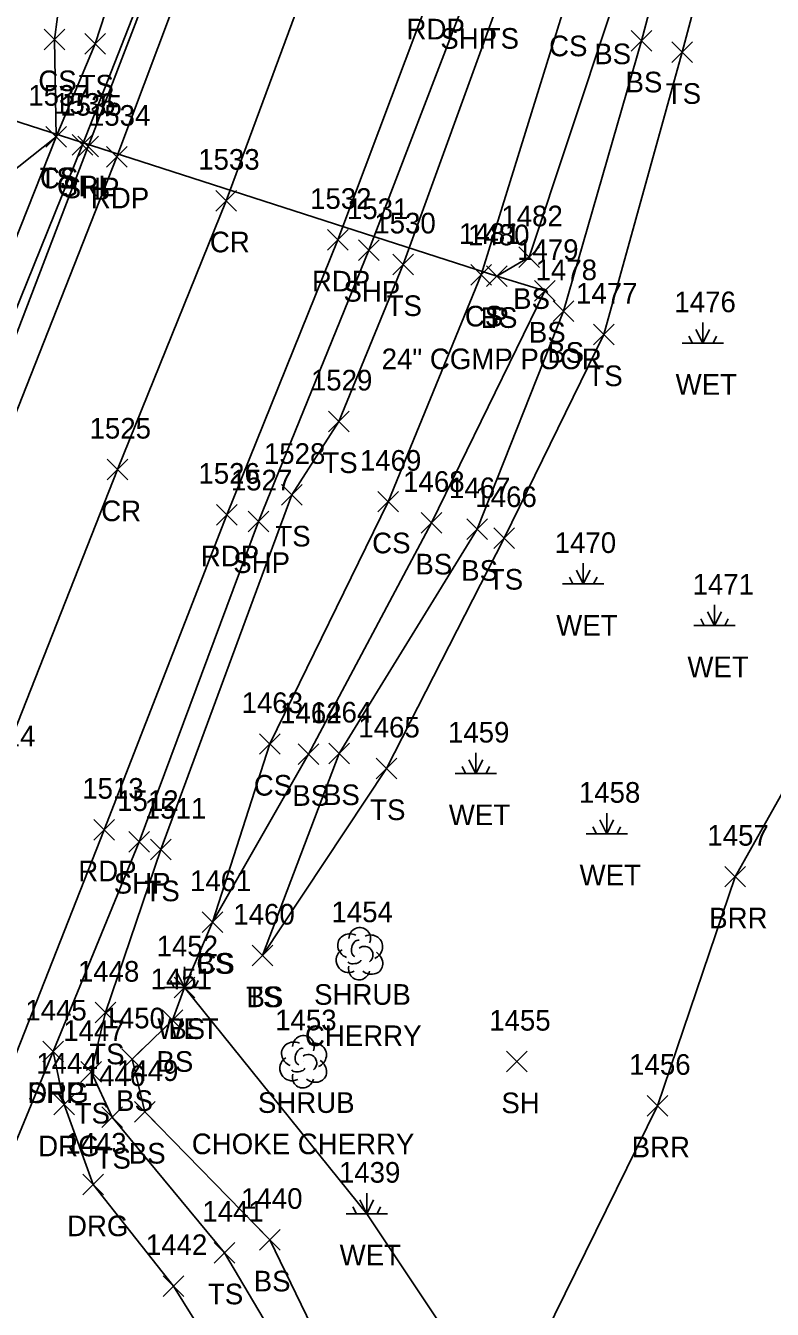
# Model space of a CAD drawing. Extents: x 1554917 to 1555870, y 813367 to 816333.
# Drawn here: x 1555209.2 to 1555281.5, y 813931.9 to 814056.2 of the extents above; entities that cross this region are included whole.
import ezdxf

# ---------------------------------------------------------------- set-up
doc = ezdxf.new("R2010")
doc.units = 0
for name, color, linetype in [('D_A', 7, 'Continuous'), ('D_C', 7, 'Continuous'), ('D_I', 7, 'Continuous'), ('D_TIC', 7, 'Continuous'), ('DCP', 7, 'Continuous'), ('L_A', 7, 'Continuous'), ('L_C', 7, 'Continuous'), ('L_I', 7, 'Continuous'), ('L_TIC', 7, 'Continuous'), ('LABL', 7, 'Continuous'), ('LELB', 7, 'Continuous'), ('LSH', 7, 'Continuous'), ('LWET', 7, 'Continuous'), ('P_A', 7, 'Continuous'), ('P_I', 7, 'Continuous'), ('P_TIC', 7, 'Continuous'), ('PET', 7, 'Continuous'), ('PRC', 7, 'Continuous'), ('PSP', 7, 'Continuous'), ('R_A', 7, 'Continuous'), ('R_I', 7, 'Continuous'), ('R_TIC', 7, 'Continuous'), ('RDG', 7, 'Continuous'), ('RGR', 7, 'Continuous')]:
    doc.layers.add(name, color=color, linetype=linetype)

msp = doc.modelspace()

# ---------------------------------------------------------------- linework, layer by layer
at = {"layer": 'D_TIC'}
for points in [[(1555253.85, 814030.94), (1555255.85, 814032.94)], [(1555255.85, 814030.94), (1555253.85, 814032.94)]]:
    msp.add_lwpolyline(points, dxfattribs=at)
at = {"layer": 'DCP'}
msp.add_lwpolyline([(1555254.85, 814031.94), (1555184.15, 814054.74)], dxfattribs=at)
at = {"layer": 'L_TIC'}
for points in [[(1555211.03, 814053.87), (1555213.03, 814055.87)], [(1555213.03, 814053.87), (1555211.03, 814055.87)], [(1555267.88, 814053.75), (1555269.88, 814055.75)], [(1555269.88, 814053.75), (1555267.88, 814055.75)], [(1555214.96, 814053.45), (1555216.96, 814055.45)], [(1555216.96, 814053.45), (1555214.96, 814055.45)], [(1555271.81, 814052.64), (1555273.81, 814054.64)], [(1555273.81, 814052.64), (1555271.81, 814054.64)], [(1555211.19, 814044.46), (1555213.19, 814046.46)], [(1555213.19, 814044.46), (1555211.19, 814046.46)], [(1555211.19, 814044.46), (1555213.19, 814046.46)], [(1555213.19, 814044.46), (1555211.19, 814046.46)], [(1555211.19, 814044.46), (1555213.19, 814046.46)], [(1555213.19, 814044.46), (1555211.19, 814046.46)], [(1555257, 814032.78), (1555259, 814034.78)], [(1555259, 814032.78), (1555257, 814034.78)], [(1555244.78, 814032.09), (1555246.78, 814034.09)], [(1555246.78, 814032.09), (1555244.78, 814034.09)], [(1555252.33, 814031.08), (1555254.33, 814033.08)], [(1555254.33, 814031.08), (1555252.33, 814033.08)], [(1555253.85, 814030.94), (1555255.85, 814032.94)], [(1555255.85, 814030.94), (1555253.85, 814032.94)], [(1555258.52, 814029.52), (1555260.52, 814031.52)], [(1555260.52, 814029.52), (1555258.52, 814031.52)], [(1555260.3, 814027.56), (1555262.3, 814029.56)], [(1555262.3, 814027.56), (1555260.3, 814029.56)], [(1555264.22, 814025.3), (1555266.22, 814027.3)], [(1555266.22, 814025.3), (1555264.22, 814027.3)], [(1555238.56, 814016.88), (1555240.56, 814018.88)], [(1555240.56, 814016.88), (1555238.56, 814018.88)], [(1555234.01, 814009.77), (1555236.01, 814011.77)], [(1555236.01, 814009.77), (1555234.01, 814011.77)], [(1555243.35, 814009.11), (1555245.35, 814011.11)], [(1555245.35, 814009.11), (1555243.35, 814011.11)], [(1555247.53, 814007.06), (1555249.53, 814009.06)], [(1555249.53, 814007.06), (1555247.53, 814009.06)], [(1555251.97, 814006.45), (1555253.97, 814008.45)], [(1555253.97, 814006.45), (1555251.97, 814008.45)], [(1555254.58, 814005.59), (1555256.58, 814007.59)], [(1555256.58, 814005.59), (1555254.58, 814007.59)], [(1555231.89, 813985.64), (1555233.89, 813987.64)], [(1555233.89, 813985.64), (1555231.89, 813987.64)], [(1555235.62, 813984.65), (1555237.62, 813986.65)], [(1555237.62, 813984.65), (1555235.62, 813986.65)], [(1555238.59, 813984.72), (1555240.59, 813986.72)], [(1555240.59, 813984.72), (1555238.59, 813986.72)], [(1555243.19, 813983.27), (1555245.19, 813985.27)], [(1555245.19, 813983.27), (1555243.19, 813985.27)], [(1555221.34, 813975.41), (1555223.34, 813977.41)], [(1555223.34, 813975.41), (1555221.34, 813977.41)], [(1555276.93, 813972.79), (1555278.93, 813974.79)], [(1555278.93, 813972.79), (1555276.93, 813974.79)], [(1555226.33, 813968.39), (1555228.33, 813970.39)], [(1555228.33, 813968.39), (1555226.33, 813970.39)], [(1555226.33, 813968.39), (1555228.33, 813970.39)], [(1555228.33, 813968.39), (1555226.33, 813970.39)], [(1555231.18, 813965.15), (1555233.18, 813967.15)], [(1555233.18, 813965.15), (1555231.18, 813967.15)], [(1555231.18, 813965.15), (1555233.18, 813967.15)], [(1555233.18, 813965.15), (1555231.18, 813967.15)], [(1555223.61, 813962.07), (1555225.61, 813964.07)], [(1555225.61, 813962.07), (1555223.61, 813964.07)], [(1555215.99, 813959.62), (1555217.99, 813961.62)], [(1555217.99, 813959.62), (1555215.99, 813961.62)], [(1555222.47, 813958.89), (1555224.47, 813960.89)], [(1555224.47, 813958.89), (1555222.47, 813960.89)], [(1555218.56, 813955.1), (1555220.56, 813957.1)], [(1555220.56, 813955.1), (1555218.56, 813957.1)], [(1555255.81, 813954.88), (1555257.81, 813956.88)], [(1555257.81, 813954.88), (1555255.81, 813956.88)], [(1555214.58, 813953.88), (1555216.58, 813955.88)], [(1555216.58, 813953.88), (1555214.58, 813955.88)], [(1555269.42, 813950.6), (1555271.42, 813952.6)], [(1555271.42, 813950.6), (1555269.42, 813952.6)], [(1555216.61, 813949.51), (1555218.61, 813951.51)], [(1555218.61, 813949.51), (1555216.61, 813951.51)], [(1555219.79, 813950), (1555221.79, 813952)], [(1555221.79, 813950), (1555219.79, 813952)], [(1555231.88, 813937.62), (1555233.88, 813939.62)], [(1555233.88, 813937.62), (1555231.88, 813939.62)], [(1555227.48, 813936.37), (1555229.48, 813938.37)], [(1555229.48, 813936.37), (1555227.48, 813938.37)]]:
    msp.add_lwpolyline(points, dxfattribs=at)
at = {"layer": 'LABL'}
msp.add_lwpolyline([(1555246.98, 813903.97), (1555255.51, 813921.27), (1555270.42, 813951.6), (1555277.93, 813973.79), (1555289.33, 813994.04), (1555300.33, 814008.73), (1555305.54, 814022.92), (1555313.64, 814041.1), (1555318.32, 814081.03), (1555326.1, 814100.25), (1555336, 814125.43)], dxfattribs=at)
at = {"layer": 'LELB'}
for points in [[(1555161.57, 813925.65), (1555168.92, 813938.89), (1555173.57, 813945.95), (1555174.16, 813952.01), (1555182.4, 813974.26), (1555190.04, 813992.11), (1555201.74, 814019.14), (1555212.19, 814045.46), (1555215.96, 814054.45), (1555221.93, 814072.78), (1555233.01, 814105.58), (1555244.12, 814126.91), (1555239.17, 814141.42), (1555241.48, 814149.75), (1555239.8, 814159.84), (1555236.73, 814168.01), (1555231.65, 814185.57), (1555238.6, 814201.71), (1555239.91, 814224.12), (1555242.5, 814231.73), (1555248.59, 814255.34), (1555259.33, 814293.88), (1555265.42, 814329.58), (1555267.14, 814335.72)], [(1555244.11, 813903.09), (1555240.76, 813916.62), (1555228.48, 813937.37), (1555217.61, 813950.51), (1555215.58, 813954.88), (1555216.99, 813960.62), (1555222.34, 813976.41), (1555235.01, 814010.77), (1555239.56, 814017.88), (1555245.78, 814033.09), (1555255.18, 814058.98), (1555268.47, 814094.07), (1555274.97, 814112.22), (1555278.17, 814116.24), (1555282.02, 814117.52), (1555286.39, 814116.11), (1555289.99, 814109.88), (1555296.54, 814106.47), (1555313.61, 814126.36), (1555333.57, 814137.64)], [(1555246.98, 813903.97), (1555242.99, 813917.76), (1555232.88, 813938.62), (1555220.79, 813951), (1555219.56, 813956.1), (1555223.47, 813959.89), (1555224.61, 813963.07), (1555227.33, 813969.39), (1555236.62, 813985.65), (1555248.53, 814008.06), (1555259.52, 814030.52), (1555254.85, 814031.94), (1555258, 814033.78), (1555265.85, 814057.48), (1555276.22, 814093.19), (1555280.35, 814112.31), (1555282.12, 814115.72), (1555282.41, 814111.98), (1555282.34, 814108.27)], [(1555232.18, 813966.15), (1555239.59, 813985.72), (1555252.97, 814007.45), (1555261.3, 814028.56), (1555268.88, 814054.75), (1555278.5, 814091.24), (1555282.34, 814108.27)], [(1555212.19, 814045.46), (1555212.03, 814054.87), (1555214.66, 814074.66), (1555228.74, 814107.66)], [(1555232.18, 813966.15), (1555244.19, 813984.27), (1555255.58, 814006.59), (1555265.22, 814026.3), (1555272.81, 814053.64), (1555282.57, 814090.32), (1555287.82, 814106.78)], [(1555227.33, 813969.39), (1555232.89, 813986.64), (1555244.35, 814010.11), (1555253.33, 814032.08), (1555261.48, 814058.25), (1555272.51, 814095.22)], [(1555212.19, 814045.46), (1555204.95, 814039.71), (1555197.69, 814022.43), (1555191.66, 814010.7), (1555185.66, 813993.85), (1555179.53, 813983.39), (1555173.8, 813970.81), (1555169.92, 813961.29), (1555164.03, 813953.38)]]:
    msp.add_lwpolyline(points, dxfattribs=at)
at = {"layer": 'LSH'}
for p, q in [((1555241.54, 813966.38), (1555241.54, 813966.38)), ((1555241.54, 813966.38), (1555241.54, 813966.38)), ((1555236.1, 813955.91), (1555236.1, 813955.91)), ((1555236.1, 813955.91), (1555236.1, 813955.91))]:
    msp.add_line(p, q, dxfattribs=at)
for centre in [(1555241.59, 813967.81), (1555236.14, 813957.35)]:
    msp.add_arc(centre, 1.05, 335.5272, 180.9563, dxfattribs=at)
for centre, major_axis, ratio, start_param, end_param in [((1555240.75, 813967.05), (1.21, -0.51), 0.895232, 1.570796, 4.712389), ((1555241.33, 813966.84), (-0.208, -0.792), 0.645439, 3.141593, 6.283185), ((1555242.58, 813966.96), (-1.14, -0.48), 0.949671, 1.570796, 4.712389), ((1555240.46, 813965.67), (0.58, -1.04), 0.959034, 3.141593, 6.283185), ((1555242.04, 813966.21), (-0.5, 0.667), 0.989748, 3.141593, 6.283185), ((1555242.54, 813965.55), (-1.09, 0.79), 0.841452, 1.570796, 4.712389), ((1555241.54, 813964.88), (0.26, 1.06), 0.942809, 1.570796, 4.712389), ((1555241.08, 813965.63), (-0.625, -0.083), 0.423636, 0, 3.141593), ((1555235.31, 813956.58), (1.21, -0.51), 0.895232, 1.570796, 4.712389), ((1555237.14, 813956.49), (-1.14, -0.48), 0.949671, 1.570796, 4.712389), ((1555235.01, 813955.2), (0.58, -1.04), 0.959034, 3.141593, 6.283185), ((1555235.89, 813956.37), (-0.208, -0.792), 0.645439, 3.141593, 6.283185), ((1555236.6, 813955.74), (-0.5, 0.667), 0.989748, 3.141593, 6.283185), ((1555235.64, 813955.16), (-0.625, -0.083), 0.423636, 0, 3.141593), ((1555237.1, 813955.08), (-1.09, 0.79), 0.841452, 1.570796, 4.712389), ((1555236.1, 813954.41), (0.26, 1.06), 0.942809, 1.570796, 4.712389)]:
    msp.add_ellipse(centre, major_axis=major_axis, ratio=ratio, start_param=start_param, end_param=end_param, dxfattribs=at)
at = {"layer": 'LWET'}
for p, q in [((1555274.8, 814025.46), (1555274.8, 814027.46)), ((1555273.8, 814025.46), (1555273.46, 814026.13)), ((1555274.8, 814025.46), (1555274.13, 814026.79)), ((1555274.8, 814025.46), (1555275.46, 814026.79)), ((1555275.8, 814025.46), (1555276.13, 814026.13)), ((1555276.8, 814025.46), (1555272.8, 814025.46)), ((1555263.23, 814002.14), (1555262.57, 814003.47)), ((1555263.23, 814002.14), (1555263.23, 814004.14)), ((1555263.23, 814002.14), (1555263.9, 814003.47)), ((1555265.23, 814002.14), (1555261.23, 814002.14)), ((1555262.23, 814002.14), (1555261.9, 814002.8)), ((1555264.23, 814002.14), (1555264.57, 814002.8)), ((1555275.94, 813998.11), (1555275.94, 814000.11)), ((1555274.94, 813998.11), (1555274.6, 813998.77)), ((1555275.94, 813998.11), (1555275.27, 813999.44)), ((1555275.94, 813998.11), (1555276.6, 813999.44)), ((1555276.94, 813998.11), (1555277.27, 813998.77)), ((1555277.94, 813998.11), (1555273.94, 813998.11)), ((1555252.83, 813983.78), (1555252.16, 813985.11)), ((1555252.83, 813983.78), (1555252.83, 813985.78)), ((1555252.83, 813983.78), (1555253.49, 813985.11)), ((1555254.83, 813983.78), (1555250.83, 813983.78)), ((1555251.83, 813983.78), (1555251.49, 813984.45)), ((1555253.83, 813983.78), (1555254.16, 813984.45)), ((1555265.5, 813977.95), (1555265.5, 813979.95)), ((1555264.5, 813977.95), (1555264.16, 813978.61)), ((1555265.5, 813977.95), (1555264.83, 813979.28)), ((1555265.5, 813977.95), (1555266.16, 813979.28)), ((1555266.5, 813977.95), (1555266.83, 813978.61)), ((1555267.5, 813977.95), (1555263.5, 813977.95)), ((1555224.61, 813963.07), (1555224.61, 813965.07)), ((1555223.61, 813963.07), (1555223.28, 813963.74)), ((1555224.61, 813963.07), (1555223.94, 813964.4)), ((1555224.61, 813963.07), (1555225.28, 813964.4)), ((1555225.61, 813963.07), (1555225.94, 813963.74)), ((1555226.61, 813963.07), (1555222.61, 813963.07)), ((1555242.27, 813941.15), (1555241.6, 813942.49)), ((1555242.27, 813941.15), (1555242.27, 813943.15)), ((1555242.27, 813941.15), (1555242.93, 813942.49)), ((1555244.27, 813941.15), (1555240.27, 813941.15)), ((1555241.27, 813941.15), (1555240.93, 813941.82)), ((1555243.27, 813941.15), (1555243.6, 813941.82))]:
    msp.add_line(p, q, dxfattribs=at)
msp.add_lwpolyline([(1555255.51, 813921.27), (1555242.27, 813941.15), (1555224.61, 813963.07)], dxfattribs=at)
at = {"layer": 'P_TIC'}
for points in [[(1555214.29, 814043.5), (1555216.29, 814045.5)], [(1555216.29, 814043.5), (1555214.29, 814045.5)], [(1555217.07, 814042.52), (1555219.07, 814044.52)], [(1555219.07, 814042.52), (1555217.07, 814044.52)], [(1555227.65, 814038.26), (1555229.65, 814040.26)], [(1555229.65, 814038.26), (1555227.65, 814040.26)], [(1555238.47, 814034.47), (1555240.47, 814036.47)], [(1555240.47, 814034.47), (1555238.47, 814036.47)], [(1555241.48, 814033.48), (1555243.48, 814035.48)], [(1555243.48, 814033.48), (1555241.48, 814035.48)], [(1555217.13, 814012.22), (1555219.13, 814014.22)], [(1555219.13, 814012.22), (1555217.13, 814014.22)], [(1555227.72, 814007.85), (1555229.72, 814009.85)], [(1555229.72, 814007.85), (1555227.72, 814009.85)], [(1555230.8, 814007.2), (1555232.8, 814009.2)], [(1555232.8, 814007.2), (1555230.8, 814009.2)], [(1555215.85, 813977.34), (1555217.85, 813979.34)], [(1555217.85, 813977.34), (1555215.85, 813979.34)], [(1555219.23, 813976.15), (1555221.23, 813978.15)], [(1555221.23, 813976.15), (1555219.23, 813978.15)], [(1555210.91, 813955.86), (1555212.91, 813957.86)], [(1555212.91, 813955.86), (1555210.91, 813957.86)]]:
    msp.add_lwpolyline(points, dxfattribs=at)
at = {"layer": 'PET'}
for points in [[(1555161.36, 813900.53), (1555183.5, 813956.99), (1555189.63, 813971.7), (1555196.36, 813987.75), (1555203.89, 814008), (1555206.01, 814012.95), (1555218.07, 814043.52), (1555227.32, 814068.19), (1555240.79, 814103.21), (1555254.41, 814137.22), (1555273.72, 814186.43), (1555286.72, 814219.57), (1555303.34, 814262.32), (1555319.11, 814302.56), (1555330.34, 814331.97)], [(1555182.57, 813892.25), (1555203.7, 813945.01), (1555216.85, 813978.34), (1555228.72, 814008.85), (1555239.47, 814035.47), (1555248.64, 814059.88), (1555262.92, 814096.01), (1555276.68, 814131.3), (1555286.36, 814156.33), (1555297.11, 814184.04), (1555306.67, 814209.51), (1555324.28, 814253.26), (1555340.35, 814293.54), (1555352.6, 814325.05)]]:
    msp.add_lwpolyline(points, dxfattribs=at)
at = {"layer": 'PRC'}
msp.add_lwpolyline([(1554976.76, 813382.18), (1554992.84, 813427.9), (1555014.07, 813486.01), (1555030.62, 813532.31), (1555046.37, 813573.08), (1555064.69, 813621.19), (1555082.41, 813667.53), (1555112.1, 813744.1), (1555110.69, 813739.79), (1555136.16, 813805.74), (1555152.52, 813846.93), (1555172.03, 813896.18), (1555193.96, 813951.2), (1555206.37, 813983.4), (1555218.13, 814013.22), (1555228.65, 814039.26), (1555237.93, 814064.31), (1555252.22, 814099.76), (1555265.8, 814135.89), (1555275.26, 814160.09), (1555297.17, 814214.77), (1555313.83, 814257.94), (1555329.72, 814298.26), (1555342.03, 814329.92)], dxfattribs=at)
at = {"layer": 'PSP'}
for points in [[(1555160.79, 813906.47), (1555173.05, 813937.33), (1555179.42, 813953.63), (1555181.24, 813957.84), (1555186.72, 813973.16), (1555194.02, 813990.9), (1555204.38, 814016.29), (1555205.03, 814017.75), (1555215.29, 814044.5), (1555224.66, 814068.93), (1555238.68, 814103.48), (1555248.96, 814130.73), (1555261.62, 814162.67), (1555270.99, 814187.05), (1555283.98, 814220.8), (1555300.65, 814263.34), (1555316.51, 814303.51), (1555327.36, 814331.38)], [(1555197.67, 813922.42), (1555211.91, 813956.86), (1555220.23, 813977.15), (1555231.8, 814008.2), (1555242.48, 814034.48), (1555251.86, 814058.97), (1555266.04, 814094.8), (1555272.79, 814112.73), (1555286.23, 814147.2), (1555300.19, 814183.09), (1555310.34, 814208.22), (1555327.38, 814252.3), (1555343.49, 814292.44), (1555355.29, 814323.57)]]:
    msp.add_lwpolyline(points, dxfattribs=at)
at = {"layer": 'R_TIC'}
for points in [[(1555213.74, 814043.68), (1555215.74, 814045.68)], [(1555215.74, 814043.68), (1555213.74, 814045.68)], [(1555210.91, 813955.86), (1555212.91, 813957.86)], [(1555212.91, 813955.86), (1555210.91, 813957.86)], [(1555211.97, 813950.71), (1555213.97, 813952.71)], [(1555213.97, 813950.71), (1555211.97, 813952.71)], [(1555214.77, 813942.97), (1555216.77, 813944.97)], [(1555216.77, 813942.97), (1555214.77, 813944.97)], [(1555222.57, 813933.14), (1555224.57, 813935.14)], [(1555224.57, 813933.14), (1555222.57, 813935.14)]]:
    msp.add_lwpolyline(points, dxfattribs=at)
at = {"layer": 'RDG'}
msp.add_lwpolyline([(1555238.98, 813899.86), (1555235.38, 813915.16), (1555223.57, 813934.14), (1555215.77, 813943.97), (1555212.97, 813951.71), (1555211.91, 813956.86)], dxfattribs=at)
at = {"layer": 'RGR'}
msp.add_lwpolyline([(1555159.27, 813917.51), (1555164.57, 813923.33), (1555172.45, 813937.61), (1555174.85, 813944.62), (1555176.88, 813950.76), (1555185.36, 813973.38), (1555192.77, 813990.92), (1555204.01, 814018.12), (1555214.74, 814044.68), (1555224.38, 814069.2), (1555237.86, 814103.71), (1555245.14, 814124.79), (1555246.27, 814138.04)], dxfattribs=at)

# ---------------------------------------------------------------- texts
at = {"layer": 'D_A'}
msp.add_text('P', height=2, dxfattribs=at).set_placement((1555254.23, 814026.94))
at = {"layer": 'D_C'}
msp.add_text('24" CGMP POOR', height=2, dxfattribs=at).set_placement((1555243.71, 814022.94))
at = {"layer": 'D_I'}
msp.add_text('1480', height=2, dxfattribs=at).set_placement((1555252.07, 814034.94))
at = {"layer": 'L_A'}
for s, p in [('TS', (1555253.59, 814053.98)), ('CS', (1555259.92, 814053.25)), ('BS', (1555264.29, 814052.48)), ('CS', (1555210.47, 814049.87)), ('BS', (1555267.32, 814049.75)), ('TS', (1555214.37, 814049.45)), ('TS', (1555271.22, 814048.64)), ('TS', (1555210.6, 814040.46)), ('CS', (1555210.63, 814040.46)), ('CS', (1555210.63, 814040.46)), ('BS', (1555256.44, 814028.78)), ('TS', (1555244.19, 814028.09)), ('CS', (1555251.77, 814027.08)), ('BS', (1555253.29, 814026.94)), ('BS', (1555257.96, 814025.52)), ('BS', (1555259.74, 814023.56)), ('TS', (1555263.63, 814021.3)), ('WET', (1555272.17, 814020.46)), ('TS', (1555237.97, 814012.88)), ('TS', (1555233.42, 814005.77)), ('CS', (1555242.79, 814005.11)), ('BS', (1555246.97, 814003.06)), ('BS', (1555251.41, 814002.45)), ('TS', (1555253.99, 814001.59)), ('WET', (1555260.61, 813997.14)), ('WET', (1555273.31, 813993.11)), ('CS', (1555231.33, 813981.64)), ('BS', (1555235.06, 813980.65)), ('BS', (1555238.03, 813980.72)), ('TS', (1555242.6, 813979.27)), ('WET', (1555250.21, 813978.78)), ('WET', (1555262.87, 813972.95)), ('TS', (1555220.75, 813971.41)), ('BRR', (1555275.42, 813968.79)), ('CS', (1555225.77, 813964.39)), ('BS', (1555225.77, 813964.39)), ('TS', (1555230.58, 813961.15)), ('BS', (1555230.62, 813961.15)), ('SHRUB', (1555237.17, 813961.38)), ('WET', (1555221.99, 813958.07)), ('BS', (1555223.05, 813958.07)), ('TS', (1555215.4, 813955.62)), ('BS', (1555221.91, 813954.89)), ('BS', (1555218, 813951.1)), ('SHRUB', (1555231.73, 813950.91)), ('SH', (1555255.3, 813950.88)), ('TS', (1555213.99, 813949.88)), ('BRR', (1555267.91, 813946.6)), ('TS', (1555216.02, 813945.51)), ('BS', (1555219.23, 813946)), ('WET', (1555239.64, 813936.15)), ('BS', (1555231.32, 813933.62)), ('TS', (1555226.89, 813932.37))]:
    msp.add_text(s, height=2, dxfattribs=at).set_placement(p)
at = {"layer": 'L_C'}
for s, p in [('CHERRY', (1555236.28, 813957.38)), ('CHOKE CHERRY', (1555225.33, 813946.91))]:
    msp.add_text(s, height=2, dxfattribs=at).set_placement(p)
at = {"layer": 'L_I'}
for s, p in [('1537', (1555209.5, 814048.46)), ('1537', (1555209.5, 814048.46)), ('1537', (1555209.5, 814048.46)), ('1530', (1555243, 814036.09)), ('1482', (1555255.3, 814036.78)), ('1481', (1555251.2, 814035.08)), ('1480', (1555252.07, 814034.94)), ('1479', (1555256.82, 814033.52)), ('1478', (1555258.61, 814031.56)), ('1477', (1555262.53, 814029.3)), ('1476', (1555272.05, 814028.46)), ('1529', (1555236.86, 814020.88)), ('1528', (1555232.31, 814013.77)), ('1469', (1555241.6, 814013.11)), ('1468', (1555245.79, 814011.06)), ('1467', (1555250.23, 814010.45)), ('1466', (1555252.78, 814009.59)), ('1470', (1555260.46, 814005.14)), ('1471', (1555273.81, 814001.11)), ('1463', (1555230.15, 813989.64)), ('1462', (1555233.88, 813988.65)), ('1464', (1555236.85, 813988.72)), ('1465', (1555241.45, 813987.27)), ('1459', (1555250.13, 813986.78)), ('1458', (1555262.8, 813980.95)), ('1511', (1555220.78, 813979.41)), ('1457', (1555275.24, 813976.79)), ('1461', (1555225.15, 813972.39)), ('1461', (1555225.15, 813972.39)), ('1460', (1555229.35, 813969.15)), ('1460', (1555229.35, 813969.15)), ('1454', (1555238.85, 813969.38)), ('1452', (1555221.92, 813966.07)), ('1452', (1555221.92, 813966.07)), ('1448', (1555214.3, 813963.62)), ('1451', (1555221.34, 813962.89)), ('1450', (1555216.78, 813959.1)), ('1447', (1555212.88, 813957.88)), ('1453', (1555233.4, 813958.91)), ('1455', (1555254.12, 813958.88)), ('1449', (1555218.09, 813954)), ('1456', (1555267.67, 813954.6)), ('1446', (1555214.86, 813953.51)), ('1439', (1555239.57, 813944.15)), ('1440', (1555230.1, 813941.62)), ('1441', (1555226.35, 813940.37))]:
    msp.add_text(s, height=2, dxfattribs=at).set_placement(p)
at = {"layer": 'P_A'}
for s, p in [('RDP', (1555246.12, 814054.88)), ('SHP', (1555249.39, 814053.97)), ('SHP', (1555212.83, 814039.5)), ('RDP', (1555215.56, 814038.52)), ('CR', (1555227.08, 814034.26)), ('RDP', (1555236.96, 814030.47)), ('SHP', (1555240.01, 814029.48)), ('CR', (1555216.56, 814008.22)), ('RDP', (1555226.21, 814003.85)), ('SHP', (1555229.34, 814003.2)), ('RDP', (1555214.34, 813973.34)), ('SHP', (1555217.77, 813972.15)), ('SHP', (1555209.44, 813951.86))]:
    msp.add_text(s, height=2, dxfattribs=at).set_placement(p)
at = {"layer": 'P_I'}
for s, p in [('1535', (1555212.6, 814047.5)), ('1534', (1555215.37, 814046.52)), ('1533', (1555225.95, 814042.26)), ('1532', (1555236.78, 814038.47)), ('1531', (1555240.35, 814037.48)), ('1525', (1555215.43, 814016.22)), ('1526', (1555225.97, 814011.85)), ('1527', (1555229.11, 814011.2)), ('1514', (1555204.24, 813986.4)), ('1513', (1555214.72, 813981.34)), ('1512', (1555218.1, 813980.15)), ('1445', (1555209.21, 813959.86))]:
    msp.add_text(s, height=2, dxfattribs=at).set_placement(p)
at = {"layer": 'R_A'}
for s, p in [('GRL', (1555212.28, 814039.68)), ('DRG', (1555209.4, 813951.86)), ('DRG', (1555210.46, 813946.71)), ('DRG', (1555213.25, 813938.97))]:
    msp.add_text(s, height=2, dxfattribs=at).set_placement(p)
at = {"layer": 'R_I'}
for s, p in [('1536', (1555211.99, 814047.68)), ('1445', (1555209.21, 813959.86)), ('1444', (1555210.27, 813954.71)), ('1443', (1555213.07, 813946.97)), ('1442', (1555220.88, 813937.14))]:
    msp.add_text(s, height=2, dxfattribs=at).set_placement(p)

doc.saveas('drawing.dxf')
